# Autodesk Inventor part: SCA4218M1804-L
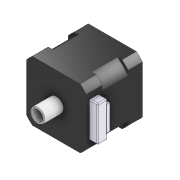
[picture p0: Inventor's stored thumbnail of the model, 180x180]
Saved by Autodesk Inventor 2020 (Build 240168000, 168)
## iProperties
Company: Nanotec GmbH & Co. KG
Created: 2021-11
Part Number: SCA4218M1804-L
Material: Generisch
Document SubType Name: Modeling
Designer: xmls36
Density: 1 g/cm^3
Appearance: Machined - Aluminum
Sending System: Autodesk Inventor 2019
Preprocessor: ST-DEVELOPER v17.2
Title: \\nano-sp\produktmanagement\Produktdokumentation\PR000085_Hohlwellenmotor_SCA20_28_42_56-L\Marketing\STEP-Datei\SCA4218M1804-L.stp
Author: marco.pinther
Revision Number: 00
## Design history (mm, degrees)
feature "SCA4218M1804-L"
body "Solid1"
